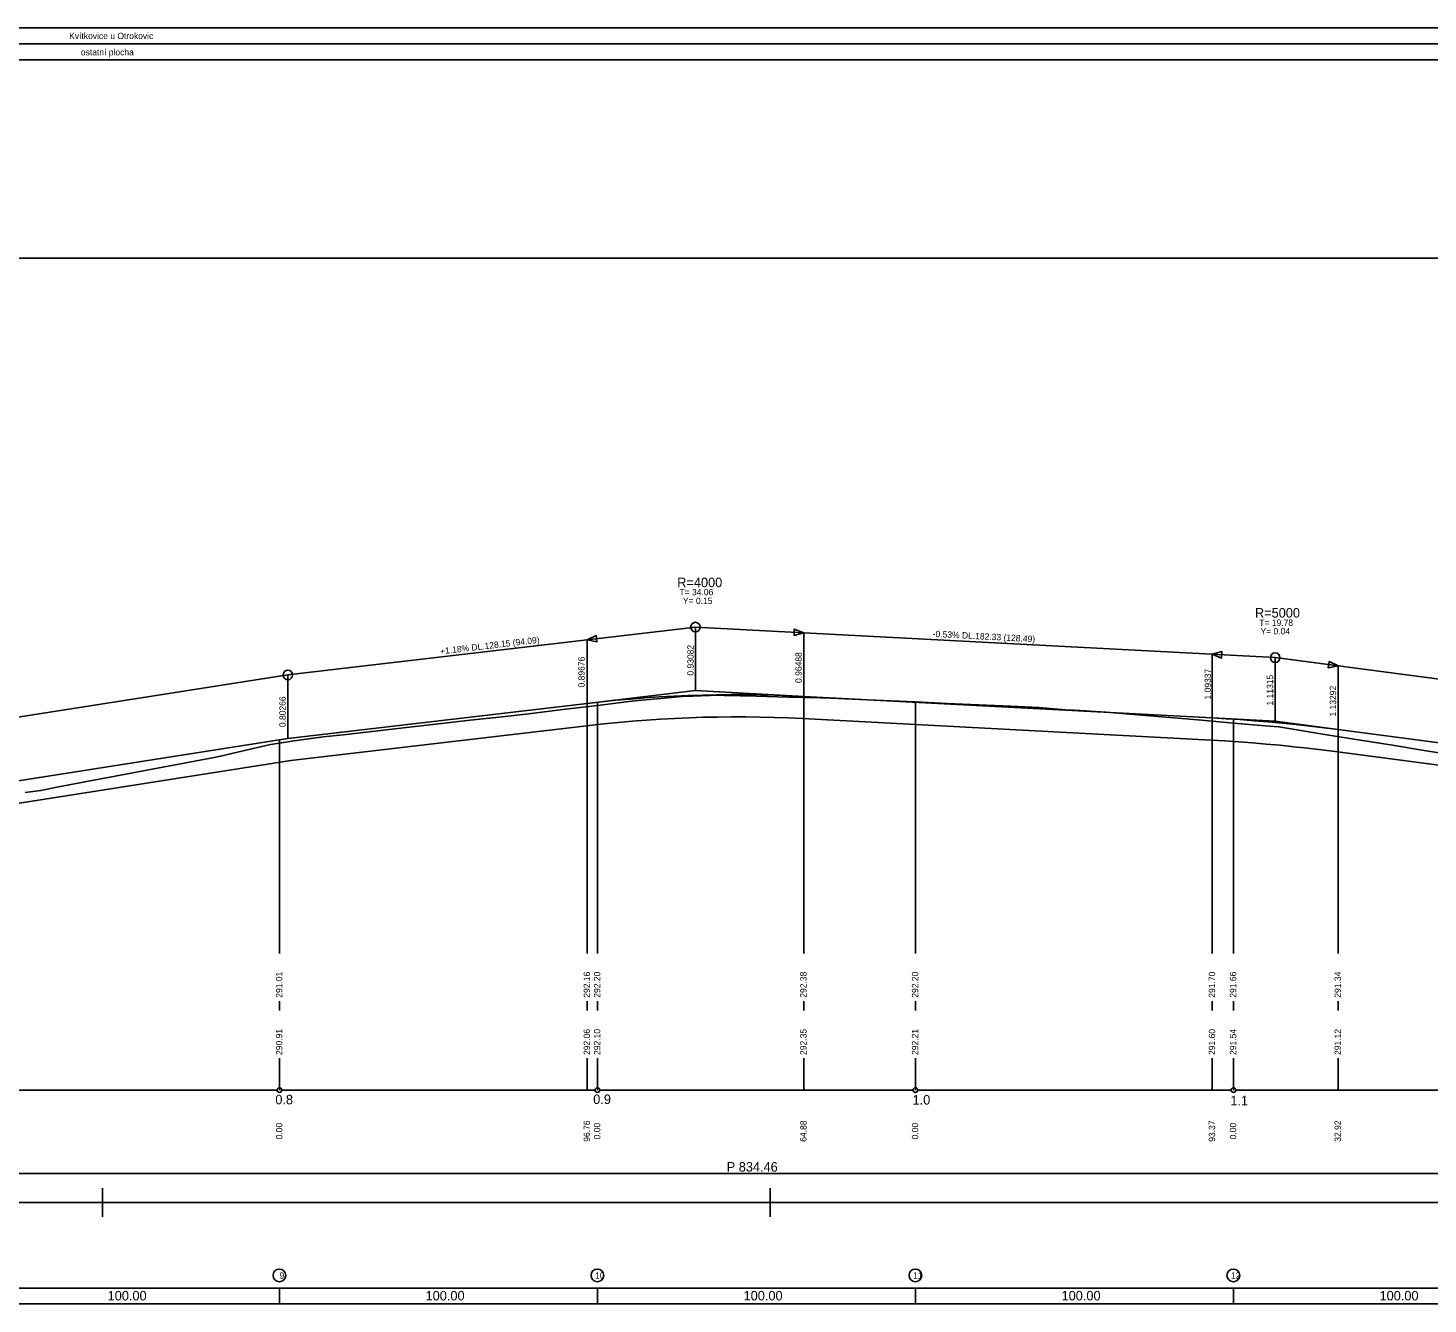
# Model space of a CAD drawing. Extents: x 1677 to 1845, y 131 to 171.
# Drawn here: x 1758.18 to 1802.21, y 130.76 to 170.89 of the extents above; entities that cross this region are included whole.
import ezdxf

# ---------------------------------------------------------------- set-up
doc = ezdxf.new("R2010")
doc.units = 0
for name, color, linetype in [('_prikopy', 7, 'Continuous'), ('KOTA', 7, 'Continuous'), ('NOVY_STAV', 7, 'Continuous'), ('NS_OBLOUK', 7, 'Continuous'), ('REZY_PO', 7, 'Continuous'), ('SESTAVY_REZU_PO', 7, 'Continuous'), ('SMEROVE_POMERY', 7, 'Continuous'), ('SVK_STAT', 7, 'Continuous'), ('TABULKY', 7, 'Continuous'), ('u_pricne_rezy', 7, 'Continuous'), ('x_formát_rám', 7, 'Continuous')]:
    doc.layers.add(name, color=color, linetype=linetype)

msp = doc.modelspace()

# ---------------------------------------------------------------- linework, layer by layer
at = {"layer": '_prikopy'}
msp.add_lwpolyline([(1747.294, 144.846), (1766.451, 147.848), (1775.845, 148.952), (1776.293, 149.002), (1776.739, 149.047), (1777.185, 149.087), (1777.632, 149.122), (1778.078, 149.151), (1778.524, 149.176), (1778.97, 149.196), (1779.416, 149.21), (1779.863, 149.219), (1780.309, 149.224), (1780.755, 149.223), (1781.201, 149.217), (1781.647, 149.206), (1782.093, 149.19), (1782.542, 149.169), (1795.387, 148.492), (1795.822, 148.467), (1796.256, 148.438), (1796.689, 148.406), (1797.122, 148.37), (1797.556, 148.33), (1797.989, 148.286), (1798.423, 148.238), (1798.856, 148.187), (1799.291, 148.131), (1822.422, 145.081)], dxfattribs=at)
at = {"layer": 'KOTA'}
for points in [[(1779.171, 150.048), (1779.171, 150.048)], [(1797.404, 149.086), (1797.404, 149.086)]]:
    msp.add_lwpolyline(points, dxfattribs=at)
at = {"layer": 'NOVY_STAV'}
for points in [[(1766.355, 150.542), (1779.171, 152.048)], [(1779.171, 150.048), (1779.171, 152.048)], [(1779.171, 152.048), (1797.404, 151.086)], [(1797.404, 149.086), (1797.404, 151.086)], [(1797.404, 151.086), (1822.422, 147.787)], [(1744.285, 147.083), (1766.355, 150.542)], [(1766.355, 148.542), (1766.355, 150.542)], [(1747.187, 145.538), (1766.355, 148.542), (1775.765, 149.648), (1776.219, 149.699), (1776.673, 149.744), (1777.127, 149.785), (1777.581, 149.82), (1778.035, 149.85), (1778.49, 149.875), (1778.944, 149.895), (1779.398, 149.91), (1779.852, 149.919), (1780.306, 149.924), (1780.76, 149.923), (1781.214, 149.917), (1781.668, 149.906), (1782.122, 149.89), (1782.577, 149.868), (1795.426, 149.191), (1795.865, 149.165), (1796.305, 149.136), (1796.744, 149.104), (1797.184, 149.067), (1797.623, 149.026), (1798.063, 148.982), (1798.502, 148.934), (1798.942, 148.882), (1799.381, 148.825), (1822.422, 145.787)], [(1775.765, 149.648), (1779.171, 150.048), (1782.577, 149.868)], [(1795.426, 149.191), (1797.404, 149.086), (1799.381, 148.825)]]:
    msp.add_lwpolyline(points, dxfattribs=at)
for centre in [(1779.171, 152.048), (1797.404, 151.086), (1766.355, 150.542)]:
    msp.add_circle(centre, 0.15, dxfattribs=at)
at = {"layer": 'NS_OBLOUK'}
for points in [[(1782.272, 151.784), (1782.577, 151.868), (1782.282, 151.984), (1782.272, 151.784)], [(1775.765, 151.648), (1776.075, 151.583), (1776.051, 151.782), (1775.765, 151.648)], [(1775.765, 149.648), (1775.765, 151.648)], [(1782.577, 149.868), (1782.577, 151.868)], [(1795.426, 151.191), (1795.72, 151.075), (1795.731, 151.275), (1795.426, 151.191)], [(1795.426, 149.191), (1795.426, 151.191)], [(1799.071, 150.766), (1799.381, 150.825), (1799.097, 150.964), (1799.071, 150.766)], [(1799.381, 148.825), (1799.381, 150.825)]]:
    msp.add_lwpolyline(points, dxfattribs=at)
for points in [[(1782.577, 151.868), (1782.282, 151.984), (1782.272, 151.784)], [(1775.765, 151.648), (1776.051, 151.782), (1776.075, 151.583)], [(1795.426, 151.191), (1795.731, 151.275), (1795.72, 151.075)], [(1799.381, 150.825), (1799.097, 150.964), (1799.071, 150.766)]]:
    msp.add_lwpolyline(points, close=True, dxfattribs=at)
at = {"layer": 'REZY_PO'}
msp.add_lwpolyline([(1758.089, 146.848), (1758.584, 146.913), (1759.089, 147.009), (1760.089, 147.199), (1761.089, 147.389), (1762.089, 147.579), (1763.089, 147.769), (1764.089, 147.959), (1764.236, 147.987), (1765.089, 148.186), (1765.807, 148.353), (1766.089, 148.398), (1766.089, 148.398), (1766.475, 148.46), (1767.089, 148.541), (1767.469, 148.591), (1768.089, 148.661), (1769.089, 148.775), (1770.089, 148.888), (1771.089, 149.002), (1772.089, 149.115), (1773.089, 149.229), (1773.841, 149.314), (1774.089, 149.344), (1775.089, 149.464), (1776.089, 149.584), (1776.089, 149.584), (1777.089, 149.704), (1777.367, 149.737), (1778.089, 149.804), (1778.735, 149.864), (1779.089, 149.876), (1779.898, 149.902), (1780.089, 149.898), (1781.089, 149.873), (1782.089, 149.848), (1783.089, 149.823), (1783.195, 149.82), (1784.089, 149.781), (1785.089, 149.737), (1786.089, 149.693), (1787.089, 149.649), (1788.089, 149.605), (1789.089, 149.561), (1789.975, 149.522), (1790.089, 149.512), (1790.934, 149.438), (1791.089, 149.43), (1792.089, 149.374), (1792.092, 149.374), (1793.089, 149.288), (1794.089, 149.202), (1795.089, 149.116), (1796.089, 149.03), (1797.089, 148.944), (1797.52, 148.906), (1798.089, 148.814), (1799.089, 148.653), (1800.089, 148.491), (1801.089, 148.329), (1802.089, 148.167), (1803.089, 148.005)], dxfattribs=at)
at = {"layer": 'SESTAVY_REZU_PO'}
for points in [[(1756.164, 137.487), (1766.014, 137.487)], [(1766.164, 137.487), (1776.014, 137.487)], [(1776.164, 137.487), (1786.014, 137.487)], [(1786.164, 137.487), (1796.014, 137.487)], [(1796.164, 137.487), (1806.014, 137.487)]]:
    msp.add_lwpolyline(points, dxfattribs=at)
for centre in [(1766.089, 137.487), (1776.089, 137.487), (1786.089, 137.487), (1796.089, 137.487)]:
    msp.add_circle(centre, 0.075, dxfattribs=at)
at = {"layer": 'SMEROVE_POMERY'}
msp.add_lwpolyline([(1686.089, 134.864), (1729.605, 134.864), (1729.605, 135.364), (1738.976, 135.364), (1738.976, 134.864), (1822.422, 134.864)], dxfattribs=at)
at = {"layer": 'SVK_STAT'}
for points in [[(1782.577, 141.787), (1782.577, 149.868)], [(1775.765, 141.787), (1775.765, 149.648)], [(1776.089, 141.787), (1776.089, 149.684)], [(1786.089, 141.787), (1786.089, 149.683)], [(1795.426, 141.787), (1795.426, 149.191)], [(1796.089, 141.787), (1796.089, 149.151)], [(1799.381, 141.787), (1799.381, 148.825)], [(1766.089, 141.787), (1766.089, 148.5)], [(1766.089, 139.987), (1766.089, 140.287)], [(1775.765, 139.987), (1775.765, 140.287)], [(1776.089, 139.987), (1776.089, 140.287)], [(1782.577, 139.987), (1782.577, 140.287)], [(1786.089, 139.987), (1786.089, 140.287)], [(1795.426, 139.987), (1795.426, 140.287)], [(1796.089, 139.987), (1796.089, 140.287)], [(1799.381, 139.987), (1799.381, 140.287)], [(1766.089, 137.487), (1766.089, 138.487)], [(1775.765, 137.487), (1775.765, 138.487)], [(1776.089, 137.487), (1776.089, 138.487)], [(1782.577, 137.487), (1782.577, 138.487)], [(1786.089, 137.487), (1786.089, 138.487)], [(1795.426, 137.487), (1795.426, 138.487)], [(1796.089, 137.487), (1796.089, 138.487)], [(1799.381, 137.487), (1799.381, 138.487)]]:
    msp.add_lwpolyline(points, dxfattribs=at)
at = {"layer": 'TABULKY'}
for points in [[(1686.089, 169.889), (1822.422, 169.889), (1822.422, 170.889), (1686.089, 170.889), (1686.089, 169.889)], [(1686.089, 170.389), (1822.422, 170.389)]]:
    msp.add_lwpolyline(points, dxfattribs=at)
at = {"layer": 'u_pricne_rezy'}
for points in [[(1686.089, 130.759), (1822.422, 130.759), (1822.422, 131.259), (1686.089, 131.259), (1686.089, 130.759)], [(1766.089, 130.759), (1766.089, 131.259)], [(1776.089, 130.759), (1776.089, 131.259)], [(1786.089, 130.759), (1786.089, 131.259)], [(1796.089, 130.759), (1796.089, 131.259)]]:
    msp.add_lwpolyline(points, dxfattribs=at)
for centre in [(1766.089, 131.659), (1776.089, 131.659), (1786.089, 131.659), (1796.089, 131.659)]:
    msp.add_circle(centre, 0.2, dxfattribs=at)
at = {"layer": 'x_formát_rám'}
for p, q in [((1760.523, 133.505), (1760.523, 134.405)), ((1781.523, 133.505), (1781.523, 134.405))]:
    msp.add_line(p, q, dxfattribs=at)
msp.add_lwpolyline([(1676.523, 133.955), (1844.523, 133.955), (1844.523, 163.655), (1676.523, 163.655)], close=True, dxfattribs=at)

# ---------------------------------------------------------------- texts
at = {"layer": 'NOVY_STAV'}
for s, rotation, p in [('-0.53% DL.182.33 (128.49)', 356.9803, (1786.628, 151.74)), ('+1.18% DL.128.15 (94.09)', 6.7039, (1771.156, 151.186)), (' 0.93082', 90, (1779.115, 150.447)), (' 1.11315', 90, (1797.341, 149.506)), (' 0.80266', 90, (1766.287, 148.827))]:
    msp.add_text(s, height=0.2, rotation=rotation, dxfattribs=at).set_placement(p)
at = {"layer": 'NS_OBLOUK'}
for s, height, p in [('R=4000', 0.3, (1778.599, 153.302)), ('T= 34.06', 0.2, (1778.671, 153.048)), ('Y= 0.15', 0.2, (1778.779, 152.775)), ('R=5000', 0.3, (1796.768, 152.346)), ('T= 19.78', 0.2, (1796.904, 152.086)), ('Y= 0.04', 0.2, (1796.943, 151.816))]:
    msp.add_text(s, height=height, dxfattribs=at).set_placement(p)
for s, p in [(' 0.89676', (1775.688, 150.074)), (' 0.96488', (1782.514, 150.216)), (' 1.09337', (1795.385, 149.695)), (' 1.13292', (1799.322, 149.159))]:
    msp.add_text(s, height=0.2, rotation=90, dxfattribs=at).set_placement(p)
at = {"layer": 'SESTAVY_REZU_PO'}
for s, p in [('0.8', (1765.96, 137.039)), ('0.9', (1775.957, 137.048)), ('1.0', (1785.999, 137.03)), ('1.1', (1795.993, 137.006))]:
    msp.add_text(s, height=0.3, dxfattribs=at).set_placement(p)
at = {"layer": 'SMEROVE_POMERY'}
msp.add_text('P 834.46', height=0.3, dxfattribs=at).set_placement((1780.155, 134.922))
at = {"layer": 'SVK_STAT'}
for s, p in [(' 291.01', (1766.179, 140.317)), (' 292.16', (1775.855, 140.317)), (' 292.20', (1776.179, 140.317)), (' 292.38', (1782.666, 140.317)), (' 292.20', (1786.179, 140.317)), (' 291.70', (1795.516, 140.317)), (' 291.66', (1796.179, 140.317)), (' 291.34', (1799.471, 140.317)), (' 290.91', (1766.179, 138.517)), (' 292.06', (1775.855, 138.517)), (' 292.10', (1776.179, 138.517)), (' 292.35', (1782.666, 138.517)), (' 292.21', (1786.179, 138.517)), (' 291.60', (1795.516, 138.517)), (' 291.54', (1796.179, 138.517)), (' 291.12', (1799.471, 138.517)), (' 96.76', (1775.855, 135.787)), (' 64.88', (1782.666, 135.787)), (' 93.37', (1795.516, 135.787)), (' 32.92', (1799.471, 135.787)), ('  0.00', (1766.179, 135.787)), ('  0.00', (1776.179, 135.787)), ('  0.00', (1786.179, 135.787)), ('  0.00', (1796.179, 135.787))]:
    msp.add_text(s, height=0.2, rotation=90, dxfattribs=at).set_placement(p)
at = {"layer": 'TABULKY'}
for s, p in [('Kvítkovice u Otrokovic', (1759.477, 170.54)), ('ostatní plocha', (1759.845, 170.027))]:
    msp.add_text(s, height=0.2, dxfattribs=at).set_placement(p)
at = {"layer": 'u_pricne_rezy'}
for s, height, p in [('9', 0.2, (1766.092, 131.554)), ('10', 0.2, (1776.016, 131.554)), ('11', 0.2, (1786.016, 131.554)), ('12', 0.2, (1796.016, 131.554)), ('100.00', 0.3, (1760.686, 130.871)), ('100.00', 0.3, (1770.686, 130.871)), ('100.00', 0.3, (1780.686, 130.871)), ('100.00', 0.3, (1790.686, 130.871)), ('100.00', 0.3, (1800.686, 130.871))]:
    msp.add_text(s, height=height, dxfattribs=at).set_placement(p)

doc.saveas('drawing.dxf')
